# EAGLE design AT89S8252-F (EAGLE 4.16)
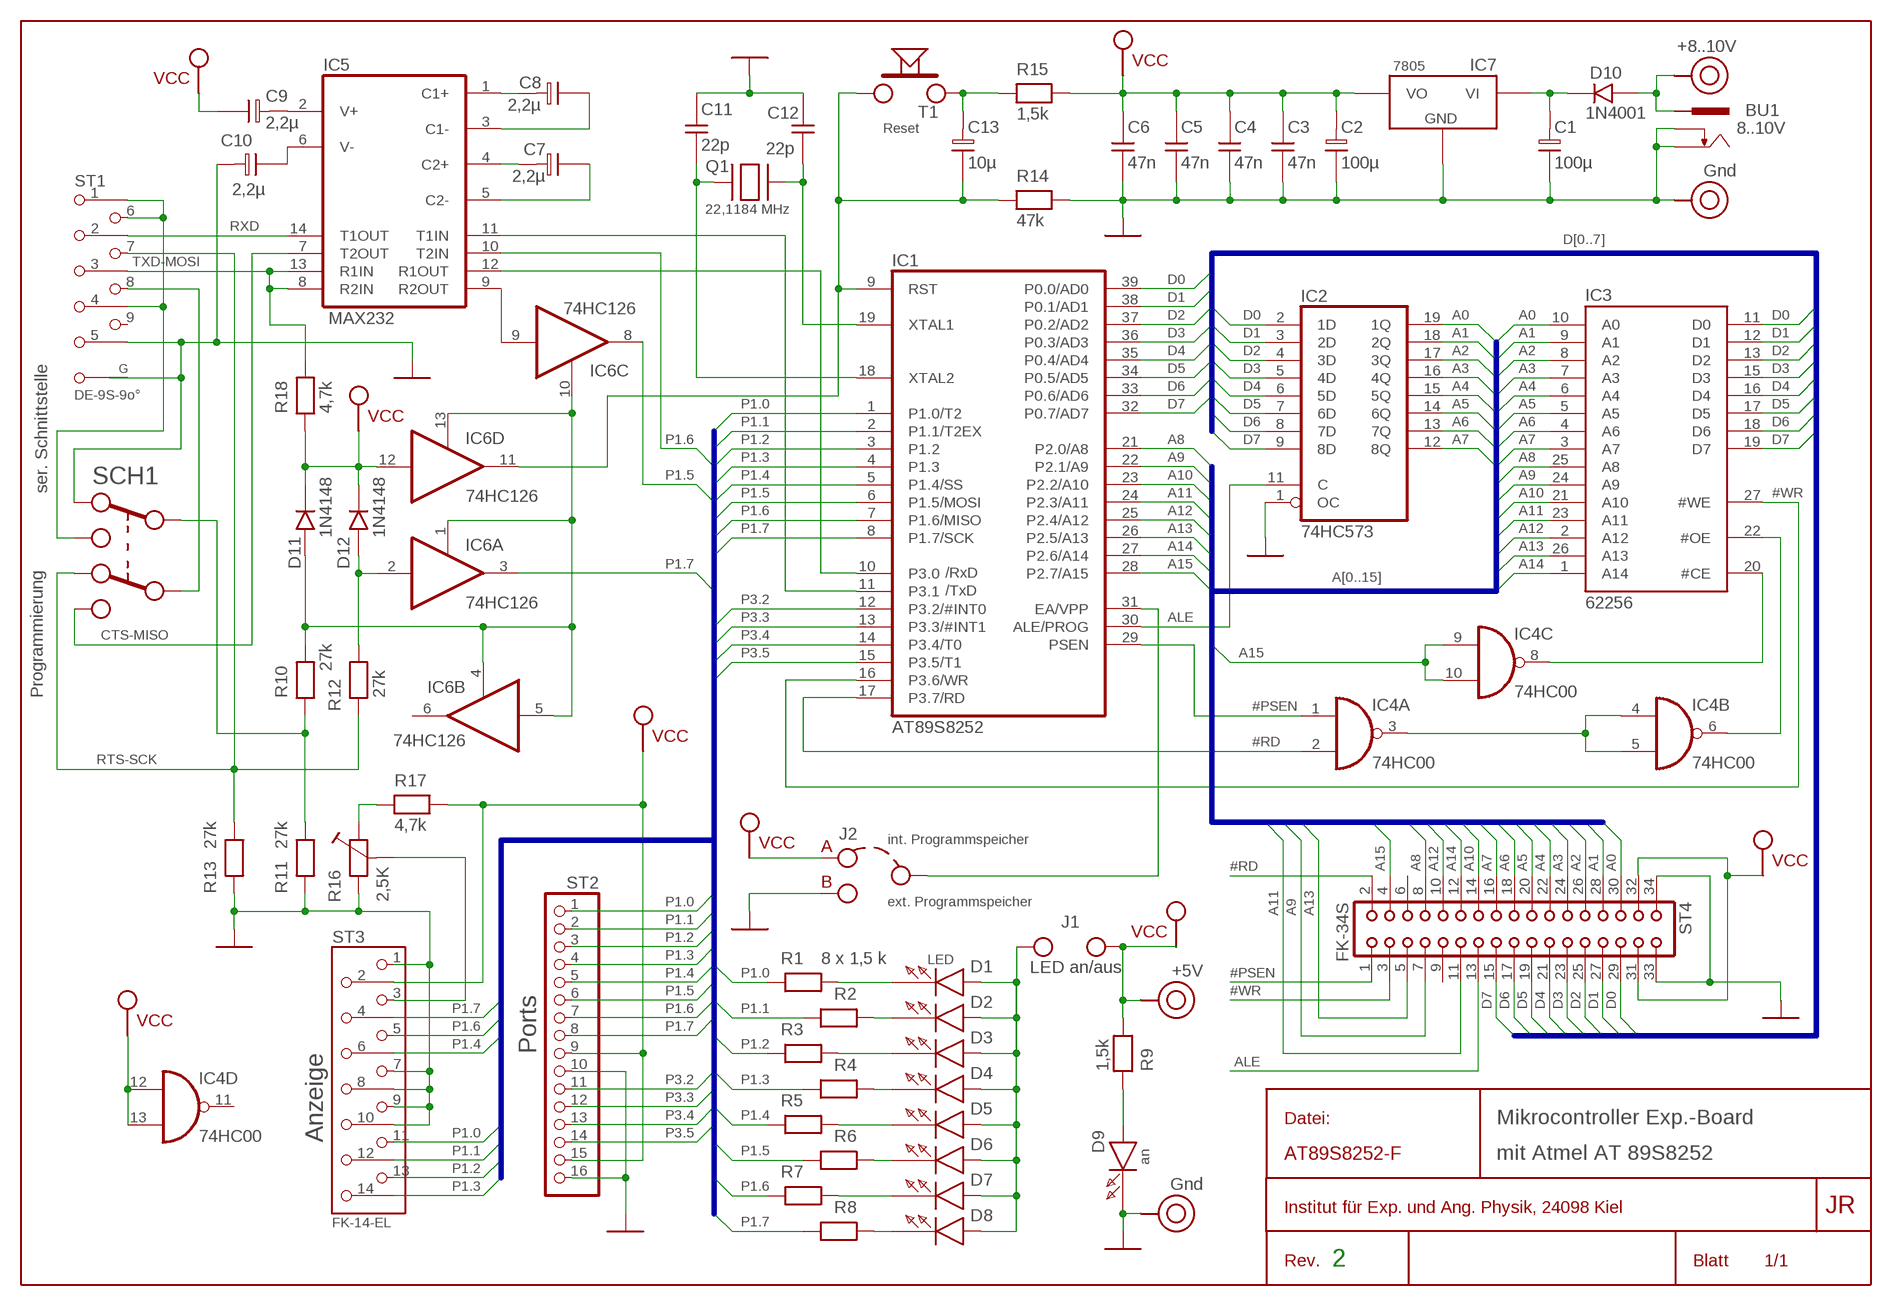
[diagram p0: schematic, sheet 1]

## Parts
BU1  8..10V  CONRAD-737992  [CONRAD-737992]
C1  100µ  ELKOR1SL  [E2,5]
C2  100µ  ELKOR1SL  [E2,5]
C3  47n  CAPR1SL  [C2,5]
C4  47n  CAPR1SL  [C2,5]
C5  47n  CAPR1SL  [C2,5]
C6  47n  CAPR1SL  [C2,5]
C7  2,2µ  ELKOR1SL  [E2,5]
C8  2,2µ  ELKOR1SL  [E2,5]
C9  2,2µ  ELKOR1SL  [E2,5]
C10  2,2µ  ELKOR1SL  [E2,5]
C11  22p  CAPR1SL  [C2,5]
C12  22p  CAPR1SL  [C2,5]
C13  10µ  ELKOR1SL  [E2,5]
D1  LEDM3-SL  [LED3]
D2  LEDM3-SL  [LED3]
D3  LEDM3-SL  [LED3]
D4  LEDM3-SL  [LED3]
D5  LEDM3-SL  [LED3]
D6  LEDM3-SL  [LED3]
D7  LEDM3-SL  [LED3]
D8  LEDM3-SL  [LED3]
D9  LEDM3-SL  [LED3]
D10  1N4001  DIODER4-SL  [D10]
D11  1N4148  DIODER3-SL  [D7,5]
D12  1N4148  DIODER3-SL  [D7,5]
IC1  AT89S8252  AT89S8252L  [LDIL-40]
IC2  74HC573  74HC573L  [LDIL-20]
IC3  62256  RAM-256KL  [LDIL-28-6]
IC4  74HC00  74HC00L  [LDIL-14]
IC5  MAX232  MAX232L  [LDIL-16]
IC6  74HC126  74HC126L  [LDIL-14]
IC7  7805  78XXTO220-SLH  [TO220H]
J1  JUMPERSL  [E1X2]
J2  DJUMPERSL  [E1X3]
Q1  22,1184 MHz  QUARZSL-V  [QV]
R1  RESR4SL  [R10]
R2  RESR4SL  [R10]
R3  RESR4SL  [R10]
R4  RESR4SL  [R10]
R5  RESR4SL  [R10]
R6  RESR4SL  [R10]
R7  RESR4SL  [R10]
R8  RESR4SL  [R10]
R9  1,5k  RESR4SL  [R10]
R10  27k  RESR4SL  [R10]
R11  27k  RESR4SL  [R10]
R12  27k  RESR4SL  [R10]
R13  27k  RESR4SL  [R10]
R14  47k  RESR4SL  [R10]
R15  1,5k  RESR4SL  [R10]
R16  2,5K  RTRIMKV-DL  [XRTRIM-V]
R17  4,7k  RESR4SL  [R10]
R18  4,7k  RESR4SL  [R10]
SCH1  SW-UM-2B  [MINSW-2B]
ST1  DE-9S-9o°  DE-9SGGHL  [D-09F90GL]
ST2  PINHD-1X16L  [1X16L]
ST3  FK-14-EL  [ML14L]
ST4  FK-34S  [ML34S]
T1  Reset  MINITASTSL  [MINITAST]
TP1  +8..10V  TPDL  [XTPV]
TP2  Gnd  TPDL  [XTPV]
TP3  +5V  TPDL  [XTPV]
TP4  Gnd  TPDL  [XTPV]

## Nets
#PSEN: IC1.29(PSEN) IC4.1(A:I0) ST4.1
#RD: IC1.17(P3.7/RD) IC4.2(A:I1) ST4.2
#WR: IC1.16(P3.6/WR) IC3.27(#WE) ST4.3
A0: IC2.19(1Q) IC3.10(A0) ST4.30
A1: IC2.18(2Q) IC3.9(A1) ST4.28
A2: IC2.17(3Q) IC3.8(A2) ST4.26
A3: IC2.16(4Q) IC3.7(A3) ST4.24
A4: IC2.15(5Q) IC3.6(A4) ST4.22
A5: IC2.14(6Q) IC3.5(A5) ST4.20
A6: IC2.13(7Q) IC3.4(A6) ST4.18
A7: IC2.12(8Q) IC3.3(A7) ST4.16
A8: IC1.21(P2.0/A8) IC3.25(A8) ST4.8
A9: IC1.22(P2.1/A9) IC3.24(A9) ST4.7
A10: IC1.23(P2.2/A10) IC3.21(A10) ST4.14
A11: IC1.24(P2.3/A11) IC3.23(A11) ST4.11
A12: IC1.25(P2.4/A12) IC3.2(A12) ST4.10
A13: IC1.26(P2.5/A13) IC3.26(A13) ST4.5
A14: IC1.27(P2.6/A14) IC3.1(A14) ST4.12
A15: IC1.28(P2.7/A15) IC4.9(C:I0) IC4.10(C:I1) ST4.4
ALE: IC1.30(ALE/PROG) IC2.11(C) ST4.13
CTS-MISO: IC5.7(T2OUT) SCH1.2B
D0: IC1.39(P0.0/AD0) IC2.2(1D) IC3.11(D0) ST4.29
D1: IC1.38(P0.1/AD1) IC2.3(2D) IC3.12(D1) ST4.27
D2: IC1.37(P0.2/AD2) IC2.4(3D) IC3.13(D2) ST4.25
D3: IC1.36(P0.3/AD3) IC2.5(4D) IC3.15(D3) ST4.23
D4: IC1.35(P0.4/AD4) IC2.6(5D) IC3.16(D4) ST4.21
D5: IC1.34(P0.5/AD5) IC2.7(6D) IC3.17(D5) ST4.19
D6: IC1.33(P0.6/AD6) IC2.8(7D) IC3.18(D6) ST4.17
D7: IC1.32(P0.7/AD7) IC2.9(8D) IC3.19(D7) ST4.15
GND: BU1.+ BU1.K C1.N C2.N C3.1 C4.1 C5.1 C6.1 C10.P C11.2 C12.2 D9.K IC2.1(OC) IC7.2(GND) J2.3 R11.1 R13.1 R14.2 R16.1 SCH1.1A ST1.5 ST1.G1 ST1.G2 ST2.10 ST2.16 ST3.1 ST3.7 ST3.8 ST3.9 ST3.10 ST4.33 ST4.34 TP2.1 TP4.1
N$1: IC1.31(EA/VPP) J2.2
N$2: SCH1.MB ST1.8
N$3: IC4.3(A:O) IC4.4(B:I0) IC4.5(B:I1)
N$4: IC3.20(#CE) IC4.8(C:O)
N$5: IC3.22(#OE) IC4.6(B:O)
N$7: C10.N IC5.6(V-)
N$8: BU1.-1 D10.A TP1.1
N$9: C1.P D10.K IC7.3(VI)
N$10: D9.A R9.1
N$11: SCH1.2A ST1.1 ST1.4 ST1.6
N$15: C8.P IC5.1(C1+)
N$16: C9.P IC5.2(V+)
N$17: C7.P IC5.4(C2+)
N$18: C8.N IC5.3(C1-)
N$19: C7.N IC5.5(C2-)
N$20: D1.K R1.1
N$21: D3.K R3.1
N$22: D5.K R5.1
N$23: D7.K R7.1
N$24: D8.K R8.1
N$25: D6.K R6.1
N$26: D4.K R4.1
N$27: D2.K R2.1
N$30: R16.2 R17.1
N$31: R10.1 R11.2 SCH1.MA
N$32: D12.A IC6.2(A:I) R12.2
N$34: IC1.11(P3.1) IC5.11(T1IN)
N$35: IC1.10(P3.0) IC5.12(R1OUT)
N$36: IC5.9(R2OUT) IC6.9(C:I)
N$37: C13.P R15.1 T1.1
N$38: C12.1 IC1.19(XTAL1) Q1.2
N$40: C11.1 IC1.18(XTAL2) Q1.1
N$42: D11.A IC6.1(A:OE) IC6.4(B:OE) IC6.5(B:I) IC6.10(C:OE) IC6.13(D:OE) R10.2
N$43: C13.N IC1.9(RST) IC6.11(D:O) R14.1 T1.2
N$44: R16.S ST3.3
N$45: D1.A D2.A D3.A D4.A D5.A D6.A D7.A D8.A J1.1
P1.0: IC1.1(P1.0/T2) R1.2 ST2.1 ST3.11
P1.1: IC1.2(P1.1/T2EX) R2.2 ST2.2 ST3.12
P1.2: IC1.3(P1.2) R3.2 ST2.3 ST3.13
P1.3: IC1.4(P1.3) R4.2 ST2.4 ST3.14
P1.4: IC1.5(P1.4/SS) R5.2 ST2.5 ST3.6
P1.5: IC1.6(P1.5/MOSI) IC6.8(C:O) R6.2 ST2.6
P1.6: IC1.7(P1.6/MISO) IC5.10(T2IN) R7.2 ST2.7 ST3.5
P1.7: IC1.8(P1.7/SCK) IC6.3(A:O) R8.2 ST2.8 ST3.4
P3.2: IC1.12(P3.2/#INT0) ST2.11
P3.3: IC1.13(P3.3/#INT1) ST2.12
P3.4: IC1.14(P3.4/T0) ST2.13
P3.5: IC1.15(P3.5/T1) ST2.14
RTS-SCK: R12.1 R13.2 SCH1.1B ST1.7
RXD: IC5.14(T1OUT) ST1.2
TXD-MOSI: IC5.8(R2IN) IC5.13(R1IN) R18.2 ST1.3
VCC: C2.P C3.2 C4.2 C5.2 C6.2 C9.N D11.K D12.K IC4.12(D:I0) IC4.13(D:I1) IC6.12(D:I) IC7.1(VO) J1.2 J2.1 R9.2 R15.2 R17.2 R18.1 ST2.9 ST2.15 ST3.2 ST4.31 ST4.32 TP3.1
Unconnected: BU1.-2 IC4.11(D:O) IC6.6(B:O) ST1.9 ST4.6 ST4.9

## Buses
D[0..7]
A[0..15]
P1.[0..7],P3.[2..5]

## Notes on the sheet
- Reset
- ser. Schnittstelle
- Programmierung
- int. Programmspeicher
- ext. Programmspeicher
- 8 x 1,5 k | LED
- LED an/aus
- Ports
- Mikrocontroller Exp.-Board
- Anzeige
- mit Atmel AT 89S8252
- an
- 2

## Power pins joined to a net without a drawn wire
GND: IC1.20(GND) IC2.10(GND) IC3.14(GND) IC4.7(P:GND) IC5.15(GND) IC6.7(P:GND)
VCC: IC1.40(VCC) IC2.20(VCC) IC3.28(VCC) IC4.14(P:VCC) IC5.16(VCC) IC6.14(P:VCC)

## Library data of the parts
BU1 = mc-parts:CONRAD-737992: FEMALE PRINT CONNECTOR DIN 45323 (34V/3A), ROKA, distributor Conrad
C1 C2 C7-C10 C13 = mc-parts:ELKO: Electrolytic capacitor
C3-C6 C11 C12 = mc-parts:CAP: Capacitor
D1-D9 = mc-parts:LED: LED
D10-D12 = mc-parts:DIODE: Diode
IC1 = MC:AT89S8252: Mikrocontroller (Atmel) mit 8kB Flash und ISP
IC2 = MC:74*573: 8-bit D latch BUS DRIVER
IC3 = MC:RAM-256K: 32x8 kBit stat. RAM
IC4 = MC:74*00: Quad 2-input NAND gate
IC5 = MC:MAX232: RS232 TRANSEIVER
IC6 = MC:74*126: Quad bus BUFFER, 3-state
IC7 = mc-parts:78XX: Postive voltage regular fix voltages
J1 = mc-parts:JUMPER: Jumper
J2 = mc-parts:DJUMPER: Alternative jumper
Q1 = mc-parts:QUARZ: Quartz
R1-R15 R17 R18 = mc-parts:RES: Resistor
R16 = mc-parts:RTRIM: Adjustable resistor
SCH1 = mc-parts:SW-UM-2
ST1 = mc-parts:DE-9SG
ST2 = mc-parts:PINHD-1X16: PIN HEADER
ST3 = mc-parts:FK-14-E: Connector with pins (male) 2 x 7 pins
ST4 = mc-parts:FK-34
T1 = mc-parts:MINITAST: Miniature push switch
TP1-TP4 = mc-parts:TP: Test or connection pin

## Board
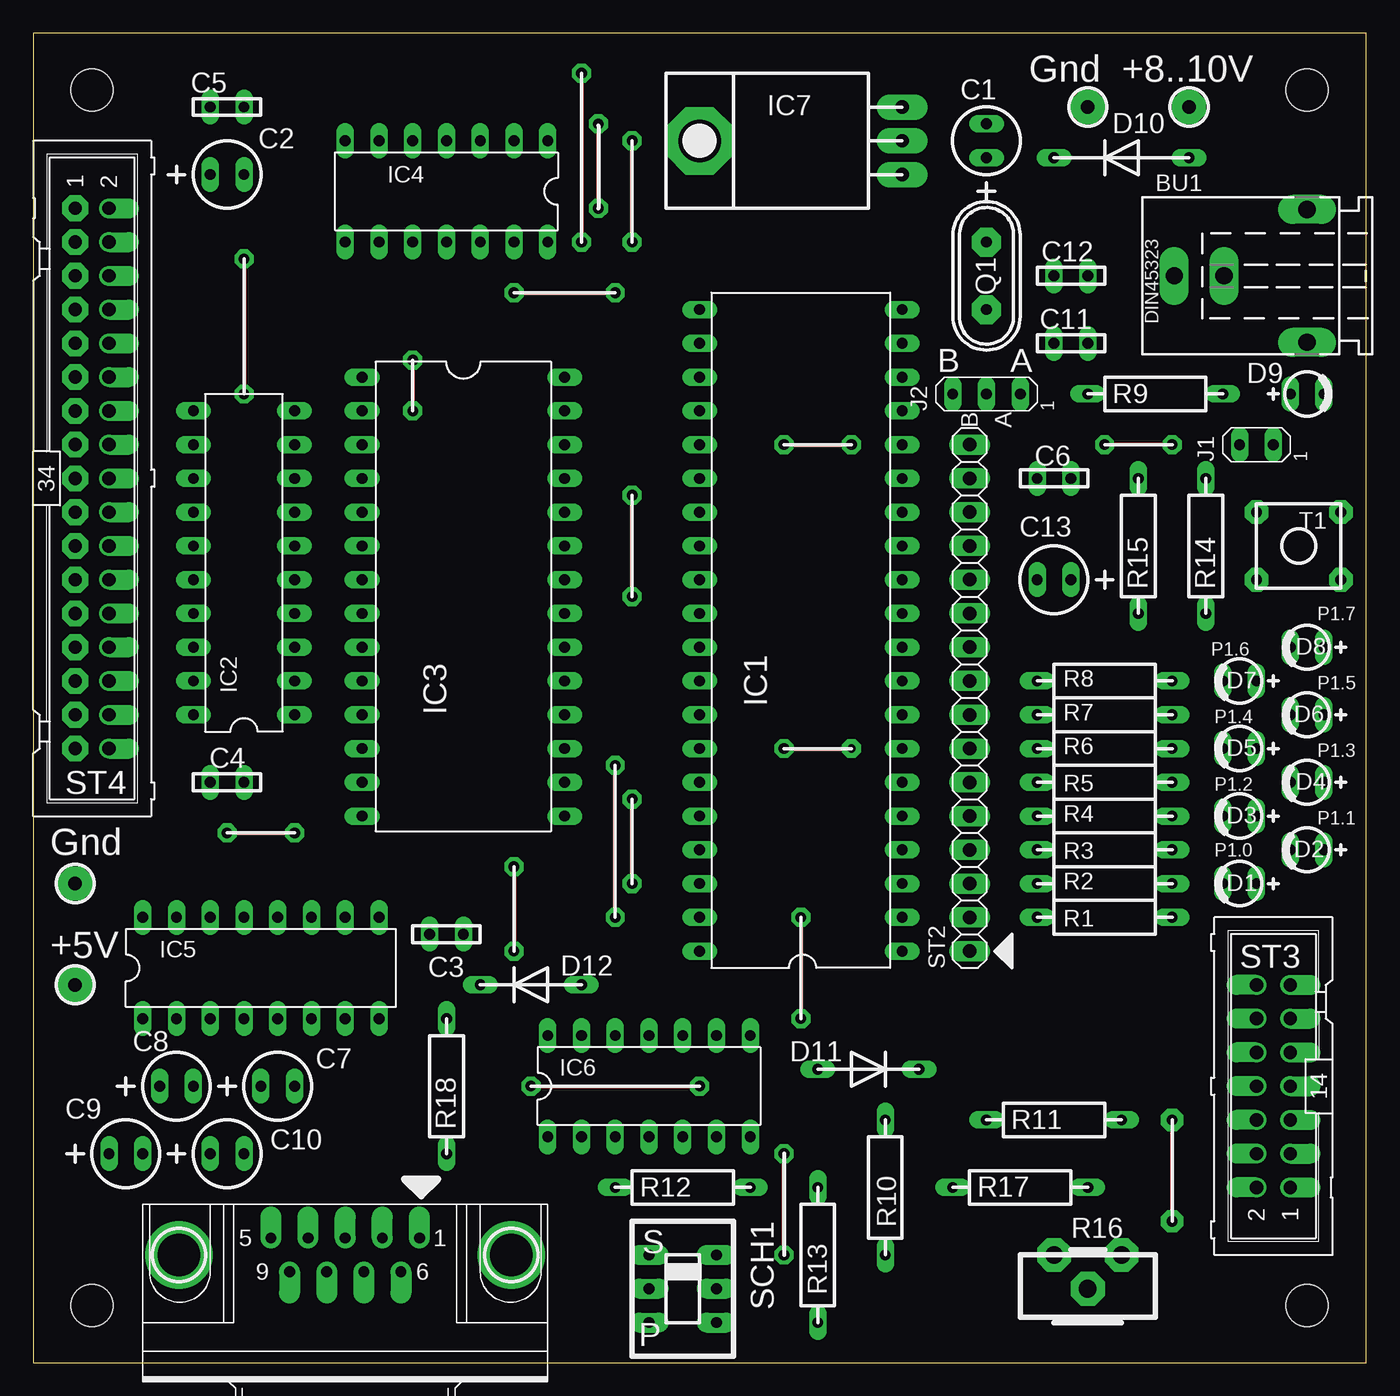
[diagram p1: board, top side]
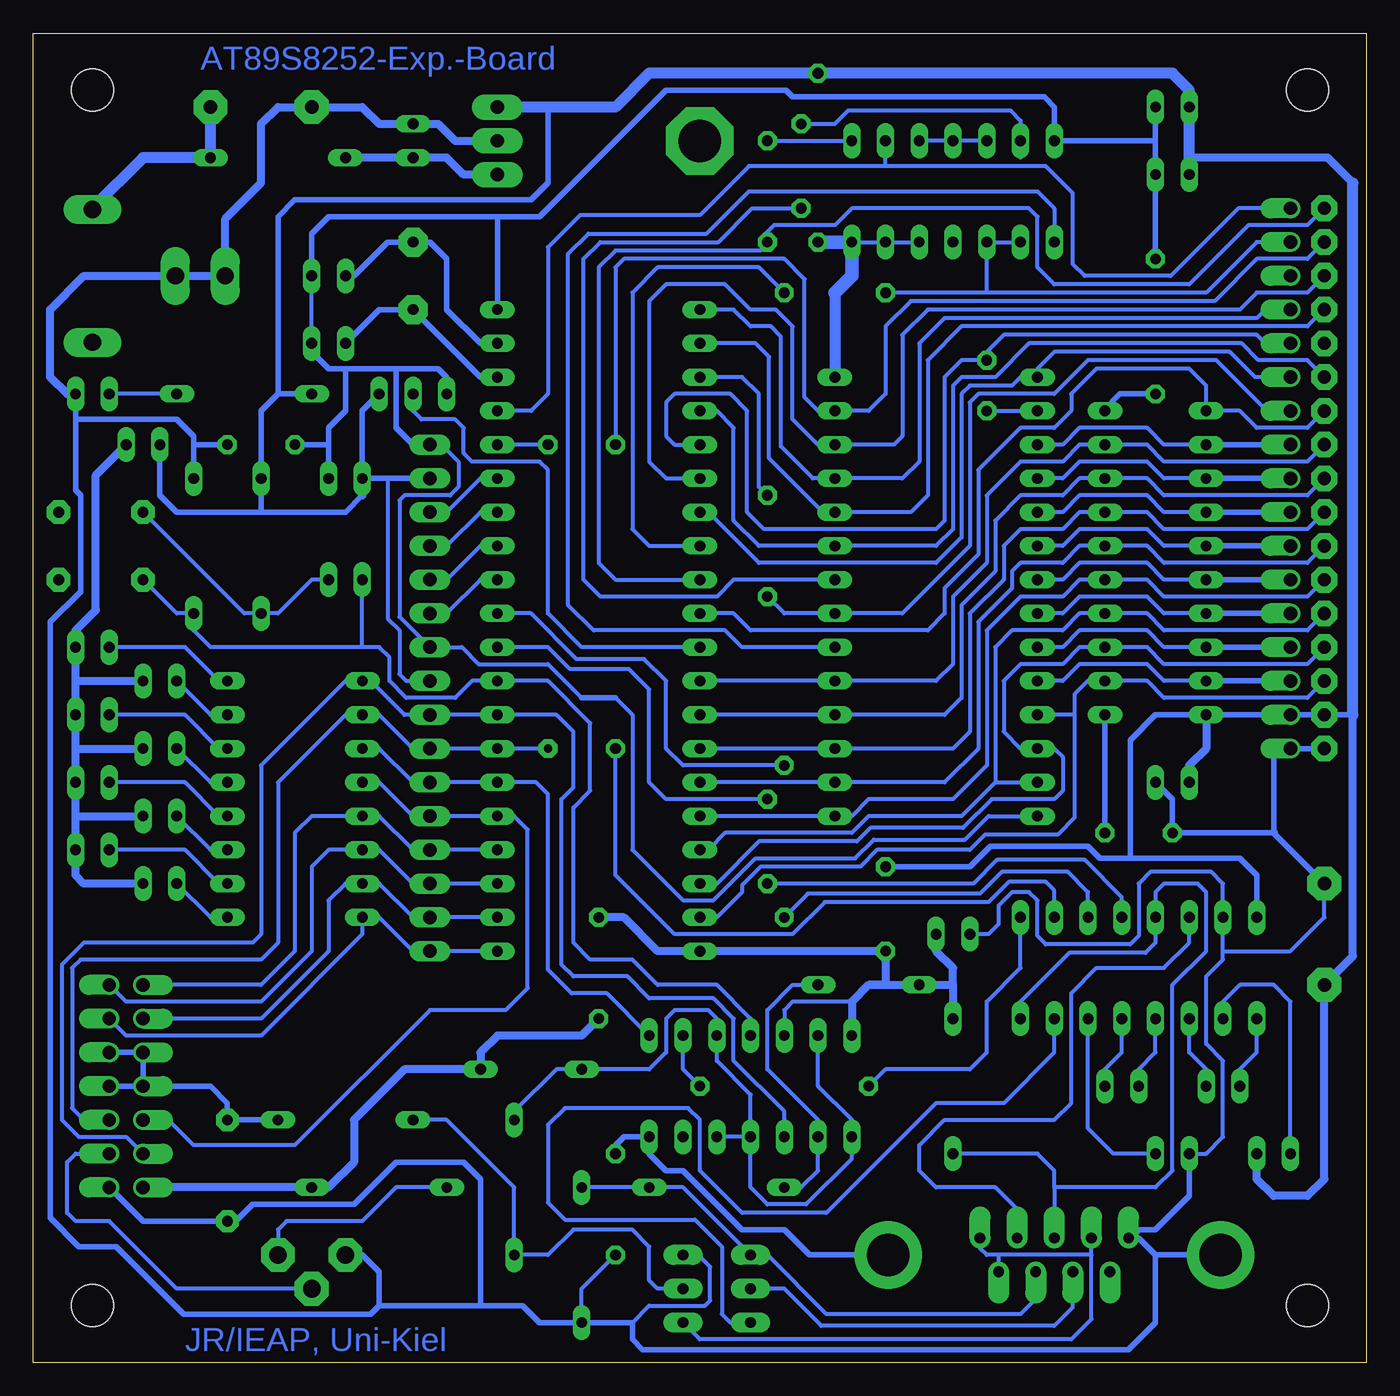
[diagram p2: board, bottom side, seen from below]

Size 100.32 x 100 mm. Coordinates in mm from the lower left corner, seen from the top.
Outline: 0,0 100.32,0 100.32,100 0,100 0,0
Copper layers (1*16): Top 0.035mm / dielectric 1.5mm / Bottom 0.035mm
Design rules "default": minimum track width 1mil, minimum drill 24mil, track to track 13mil, track to pad 13mil, pad to pad 12mil, via to via 12mil, smd to smd 8mil, copper to edge 20mil, drill to drill 8mil, minimum pad ring 10mil, minimum via ring 8mil, stop-mask expansion 4mil, vias tented up to drill 0mil, thermal gap 10mil
Holes 3.17 mm at 4.43,4.28 4.43,95.72 95.87,95.72 95.87,4.28

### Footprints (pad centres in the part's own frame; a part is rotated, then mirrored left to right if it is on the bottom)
CONRAD-737992 = drill 1.3 pad 2.184 long: + 0,10; -1 5,0; -2 -5,0; K 0,6.25
E2,5 = drill 0.813 pad 1.27 long: N 1.27,0; P -1.27,0
C2,5 = drill 0.813 pad 1.27 long: 1 1.27,0; 2 -1.27,0
LED3 = drill 0.813 long: A 1.27,0; K -1.27,0
D10 = drill 0.813 long: A 5.08,0; K -5.08,0
D7,5 = drill 0.813 long: A 3.81,0; K -3.81,0
LDIL-40 = drill 0.813 long: 1 -24.13,-7.62; 2 -21.59,-7.62; 3 -19.05,-7.62; 4 -16.51,-7.62; 5 -13.97,-7.62; 6 -11.43,-7.62; 7 -8.89,-7.62; 8 -6.35,-7.62; 9 -3.81,-7.62; 10 -1.27,-7.62; 11 1.27,-7.62; 12 3.81,-7.62; 13 6.35,-7.62; 14 8.89,-7.62; 15 11.43,-7.62; 16 13.97,-7.62; 17 16.51,-7.62; 18 19.05,-7.62; 19 21.59,-7.62; 20 24.13,-7.62; 21 24.13,7.62; 22 21.59,7.62; 23 19.05,7.62; 24 16.51,7.62; 25 13.97,7.62; 26 11.43,7.62; 27 8.89,7.62; 28 6.35,7.62; 29 3.81,7.62; 30 1.27,7.62; 31 -1.27,7.62; 32 -3.81,7.62; 33 -6.35,7.62; 34 -8.89,7.62; 35 -11.43,7.62; 36 -13.97,7.62; 37 -16.51,7.62; 38 -19.05,7.62; 39 -21.59,7.62; 40 -24.13,7.62
LDIL-20 = drill 0.813 long: 1 -11.43,-3.81; 2 -8.89,-3.81; 3 -6.35,-3.81; 4 -3.81,-3.81; 5 -1.27,-3.81; 6 1.27,-3.81; 7 3.81,-3.81; 8 6.35,-3.81; 9 8.89,-3.81; 10 11.43,-3.81; 11 11.43,3.81; 12 8.89,3.81; 13 6.35,3.81; 14 3.81,3.81; 15 1.27,3.81; 16 -1.27,3.81; 17 -3.81,3.81; 18 -6.35,3.81; 19 -8.89,3.81; 20 -11.43,3.81
LDIL-28-6 = drill 0.813 long: 1 -16.51,-7.62; 2 -13.97,-7.62; 3 -11.43,-7.62; 4 -8.89,-7.62; 5 -6.35,-7.62; 6 -3.81,-7.62; 7 -1.27,-7.62; 8 1.27,-7.62; 9 3.81,-7.62; 10 6.35,-7.62; 11 8.89,-7.62; 12 11.43,-7.62; 13 13.97,-7.62; 14 16.51,-7.62; 15 16.51,7.62; 16 13.97,7.62; 17 11.43,7.62; 18 8.89,7.62; 19 6.35,7.62; 20 3.81,7.62; 21 1.27,7.62; 22 -1.27,7.62; 23 -3.81,7.62; 24 -6.35,7.62; 25 -8.89,7.62; 26 -11.43,7.62; 27 -13.97,7.62; 28 -16.51,7.62
LDIL-14 = drill 0.813 long: 1 -7.62,-3.81; 2 -5.08,-3.81; 3 -2.54,-3.81; 4 0,-3.81; 5 2.54,-3.81; 6 5.08,-3.81; 7 7.62,-3.81; 8 7.62,3.81; 9 5.08,3.81; 10 2.54,3.81; 11 0,3.81; 12 -2.54,3.81; 13 -5.08,3.81; 14 -7.62,3.81
LDIL-16 = drill 0.813 long: 1 -8.89,-3.81; 2 -6.35,-3.81; 3 -3.81,-3.81; 4 -1.27,-3.81; 5 1.27,-3.81; 6 3.81,-3.81; 7 6.35,-3.81; 8 8.89,-3.81; 9 8.89,3.81; 10 6.35,3.81; 11 3.81,3.81; 12 1.27,3.81; 13 -1.27,3.81; 14 -3.81,3.81; 15 -6.35,3.81; 16 -8.89,3.81
TO220H = drill 1 pad 1.905 long: 1 2.54,-10.16; 2 0,-10.16; 3 -2.54,-10.16 | drill 3.2 pad 5.08 octagon: KK 0,5.08
E1X2 = drill 0.813 long: 1 0,-1.27; 2 0,1.27
E1X3 = drill 0.813 long: 1 0,-2.54; 2 0,0; 3 0,2.54
QV = drill 0.813 pad 2.184 octagon: 1 -2.54,0; 2 2.54,0
R10 = drill 0.813 long: 1 -5.08,0; 2 5.08,0
XRTRIM-V = drill 1.321 pad 2.54 octagon: 1 -2.54,-2.54; 2 -2.54,2.54; S 0,0
MINSW-2B = drill 0.813 pad 1.499 long: 1A -2.54,2.54; 1B -2.54,-2.54; 2A 2.54,2.54; 2B 2.54,-2.54; MA 0,2.54; MB 0,-2.54
D-09F90GL = drill 0.813 pad 1.575 offset: 1 -5.588,-1.27; 2 -2.794,-1.27; 3 0,-1.27; 4 2.794,-1.27; 5 5.588,-1.27; 6 -4.191,1.27; 7 -1.397,1.27; 8 1.397,1.27; 9 4.191,1.27 | drill 3.2 pad 5.08 round: G1 -12.5,0; G2 12.5,0
1X16L = drill 1.016 long: 1 -19.05,0; 2 -16.51,0; 3 -13.97,0; 4 -11.43,0; 5 -8.89,0; 6 -6.35,0; 7 -3.81,0; 8 -1.27,0; 9 1.27,0; 10 3.81,0; 11 6.35,0; 12 8.89,0; 13 11.43,0; 14 13.97,0; 15 16.51,0; 16 19.05,0
ML14L = drill 1 pad 1.422 offset: 1 -7.62,-1.27; 2 -7.62,1.27; 3 -5.08,-1.27; 4 -5.08,1.27; 5 -2.54,-1.27; 6 -2.54,1.27; 7 0,-1.27; 8 0,1.27; 9 2.54,-1.27; 10 2.54,1.27; 11 5.08,-1.27; 12 5.08,1.27; 13 7.62,-1.27; 14 7.62,1.27
ML34S = drill 1 pad 1.93 octagon: 1 -20.32,-1.27; 3 -17.78,-1.27; 5 -15.24,-1.27; 7 -12.7,-1.27; 9 -10.16,-1.27; 11 -7.62,-1.27; 13 -5.08,-1.27; 15 -2.54,-1.27; 17 0,-1.27; 19 2.54,-1.27; 21 5.08,-1.27; 23 7.62,-1.27; 25 10.16,-1.27; 27 12.7,-1.27; 29 15.24,-1.27; 31 17.78,-1.27; 33 20.32,-1.27 | drill 1 pad 1.422 offset: 2 -20.32,1.27; 4 -17.78,1.27; 6 -15.24,1.27; 8 -12.7,1.27; 10 -10.16,1.27; 12 -7.62,1.27; 14 -5.08,1.27; 16 -2.54,1.27; 18 0,1.27; 20 2.54,1.27; 22 5.08,1.27; 24 7.62,1.27; 26 10.16,1.27; 28 12.7,1.27; 30 15.24,1.27; 32 17.78,1.27; 34 20.32,1.27
MINITAST = drill 0.813 pad 1.778 octagon: 1 -2.54,-3.175; 2 2.54,-3.175; 3 2.54,3.175; 4 -2.54,3.175
XTPV = drill 1.016 pad 2.54 octagon: 1 0,0

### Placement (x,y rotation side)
BU1  95.87,81.75 90 top
C1  71.74,91.91 90 top
C2  14.59,89.37 0 top
C3  31.1,32.22 180 top
C4  14.59,43.65 0 top
C5  14.59,94.45 0 top
C6  76.82,66.51 0 top
C7  18.4,20.79 0 top
C8  10.78,20.79 0 top
C9  6.97,15.71 0 top
C10  14.59,15.71 0 top
C11  78.09,76.67 180 top
C12  78.09,81.75 180 top
C13  76.82,58.89 180 top
D1  90.79,36.03 0 top
D2  95.87,38.57 0 top
D3  90.79,41.11 0 top
D4  95.87,43.65 0 top
D5  90.79,46.19 0 top
D6  95.87,48.73 0 top
D7  90.79,51.27 0 top
D8  95.87,53.81 0 top
D9  95.87,72.86 180 top
D10  81.9,90.64 0 top
D11  62.85,22.06 180 top
D12  37.45,28.41 0 top
IC1  57.77,55.08 90 top
IC2  15.86,60.16 90 top
IC3  32.37,57.62 270 top
IC4  31.1,88.1 180 top
IC5  17.13,29.68 0 top
IC6  46.34,20.79 0 top
IC7  55.23,91.91 90 top
J1  92.06,69.05 90 top
J2  71.74,72.86 90 top
Q1  71.74,81.75 90 top
R1  80.63,33.49 180 top
R2  80.63,36.03 180 top
R3  80.63,38.57 180 top
R4  80.63,41.11 180 top
R5  80.63,43.65 180 top
R6  80.63,46.19 180 top
R7  80.63,48.73 180 top
R8  80.63,51.27 180 top
R9  84.44,72.86 180 top
R10  64.12,13.17 90 top
R11  76.82,18.25 180 top
R12  48.88,13.17 180 top
R13  59.04,8.09 90 top
R14  88.25,61.43 90 top
R15  83.17,61.43 90 top
R16  79.36,5.55 270 top
R17  74.28,13.17 0 top
R18  31.1,20.79 270 top
SCH1  48.88,5.55 270 top
ST1  23.48,8.09 180 top
ST2  70.47,50 90 top
ST3  93.33,20.79 90 top
ST4  4.43,66.51 270 top
T1  95.23,61.43 270 top
TP1  86.98,94.45 0 top
TP2  79.36,94.45 0 top
TP3  3.16,28.41 0 top
TP4  3.16,36.03 0 top
U$21  [IEAP-TOP]  not placed on the board

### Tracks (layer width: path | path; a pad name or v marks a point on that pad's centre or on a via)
#PSEN  (via drill 0.8 pad 1.42)
  Top 0.305: v45.07,84.29 v45.07,91.91
  Bottom 0.305: IC1.29 56.5,58.89 57.77,60.16 57.77,82.39 56.5,83.66 45.58,83.66 45.07,84.16 v45.07,84.29 45.2,84.42 45.2,84.92 44.56,85.56 39.99,85.56 38.72,86.83 25.39,86.83 24.75,86.19 24.75,82.39 23.48,81.11 13.32,81.11 8.88,85.56 4.43,85.56 ST4.1 | v45.07,91.91 IC4.1
#RD
  Bottom 0.305: IC1.17 62.85,71.59 61.58,72.86 61.58,83.91 59.17,86.32 50.15,86.32 46.47,90 36.18,90 | ST4.2 9.64,86.83 14.72,81.75 21.19,81.75 22.08,82.64 22.08,87.97 24.12,90 36.18,90 | 36.18,90 IC4.2
#WR  (via drill 0.8 pad 1.42)
  Top 0.305: v56.5,69.05 v61.58,69.05
  Bottom 0.305: v61.58,69.05 IC1.16 | v56.5,69.05 56.5,82.39 55.86,83.02 43.8,83.02 42.28,81.5 42.28,72.61 41.26,71.59 IC3.27 37.45,71.59 36.18,72.86 36.18,77.94 34.27,79.84 11.41,79.84 8.24,83.02 4.43,83.02 ST4.3
A0
  Bottom 0.305: IC2.19 15.22,51.27 16.5,52.54 21.57,52.54 22.85,51.27 IC3.10
  Bottom 0.406: ST4.30 IC2.19
A1
  Bottom 0.305: IC2.18 15.22,53.81 16.5,55.08 21.57,55.08 22.85,53.81 IC3.9
  Bottom 0.406: ST4.28 IC2.18
A2
  Bottom 0.305: IC2.17 15.22,56.35 16.5,57.62 21.57,57.62 22.85,56.35 IC3.8
  Bottom 0.406: ST4.26 IC2.17
A3
  Bottom 0.305: IC2.16 15.22,58.89 16.5,60.16 21.57,60.16 22.85,58.89 IC3.7
  Bottom 0.406: ST4.24 IC2.16
A4
  Bottom 0.305: IC2.15 15.22,61.43 16.5,62.7 21.57,62.7 22.85,61.43 IC3.6
  Bottom 0.406: ST4.22 IC2.15
A5
  Bottom 0.305: IC2.14 15.22,63.97 16.5,65.24 21.57,65.24 22.85,63.97 IC3.5
  Bottom 0.406: ST4.20 IC2.14
A6
  Bottom 0.305: IC2.13 15.22,66.51 16.5,67.78 21.57,67.78 22.85,66.51 IC3.4
  Bottom 0.406: ST4.18 IC2.13
A7
  Bottom 0.305: IC2.12 15.22,69.05 16.5,70.32 21.57,70.32 22.85,69.05 IC3.3
  Bottom 0.406: ST4.16 IC2.12
A8
  Bottom 0.305: IC1.21 47.61,79.21 46.34,77.94 44.82,77.94 44.05,77.18 44.05,68.92 41.64,66.51 IC3.25 34.91,66.51 33.64,67.78 33.64,76.67 31.73,78.58 8.24,78.58 7.61,79.21 ST4.8
A9
  Bottom 0.305: IC1.22 45.96,76.67 44.94,75.65 44.94,68.03 40.88,63.97 IC3.24 34.27,63.97 33,65.24 33,75.4 30.46,77.94 4.43,77.94 ST4.7
A10  (via drill 0.8 pad 1.42)
  Top 0.305: v45.07,57.62 v45.07,65.24
  Bottom 0.305: v45.07,57.62 43.8,56.35 IC3.21 34.91,56.35 29.83,61.43 29.83,72.22 29.2,72.86 23.48,72.86 20.94,75.4 11.29,75.4 7.48,71.59 ST4.14 | v45.07,65.24 45.7,65.88 45.7,72.86 46.97,74.13 IC1.23
A11
  Bottom 0.305: IC1.24 48.88,71.59 47.61,70.32 47.61,63.34 45.7,61.43 IC3.23 32.37,61.43 31.1,62.7 31.1,73.5 30.46,74.13 27.93,74.13 25.39,76.67 9.38,76.67 8.11,75.4 4.43,75.4 ST4.11
A12  (via drill 0.8 pad 1.42)
  Top 0.305: v28.56,75.4 v28.56,71.59
  Bottom 0.305: 24.12,71.59 IC3.2 v28.56,71.59 | IC1.25 52.05,69.05 52.69,69.69 52.69,72.22 52.05,72.86 47.86,72.86 46.59,71.59 46.59,63.97 45.32,62.7 32.37,62.7 31.73,63.34 31.73,74.13 30.46,75.4 v28.56,75.4 28.56,76.03 27.29,77.3 8.24,77.3 7.61,76.67 ST4.10
A13
  Bottom 0.305: IC1.26 52.69,66.51 53.96,67.78 53.96,79.84 52.69,81.11 48.24,81.11 46.34,79.21 44.43,79.21 43.16,77.94 43.16,70.95 41.26,69.05 IC3.26 35.54,69.05 34.91,69.69 34.91,77.3 33,79.21 9.51,79.21 8.24,80.48 4.43,80.48 ST4.5
A14
  Bottom 0.305: IC1.27 49.52,63.97 45.7,60.16 32.37,60.16 30.46,62.06 30.46,72.86 29.83,73.5 26.66,73.5 26.02,74.13 IC3.1 24.75,74.77 23.48,76.03 10.27,76.03 8.37,74.13 ST4.12
A15  (via drill 0.8 pad 1.42)
  Top 0.305: v36.18,80.48 v43.8,80.48
  Bottom 0.305: IC1.28 53.96,61.43 55.23,62.7 55.23,80.48 53.32,82.39 45.7,82.39 v43.8,80.48 | 28.56,80.48 v36.18,80.48 | 28.56,80.48 12.05,80.48 8.24,84.29 ST4.4 | IC4.9 IC4.10 28.56,80.48
ALE
  Bottom 0.305: IC1.30 47.61,56.35 46.34,55.08 33,55.08 31.73,56.35 31.73,58.25 29.2,60.8 29.2,67.14 26.02,70.32 23.48,70.32 22.21,71.59 22.21,72.86 20.3,74.77 13.32,74.77 12.05,73.5 IC2.11 9.51,71.59 8.24,70.32 4.43,70.32 ST4.13
CTS-MISO
  Bottom 0.305: SCH1.2B 47.86,3.01 48.5,3.64 48.5,8.73 50.53,10.76 60.31,10.76 61.58,12.03 61.58,17.87 60.31,19.14 51.04,19.14 50.15,18.25 50.15,14.44 46.97,11.27 40.62,11.27 32.37,19.52 27.29,19.52 23.48,23.33 IC5.7
D0
  Bottom 0.305: IC1.39 48.88,33.49 46.97,35.39 46.97,35.9 45.58,37.3 38.09,37.3 36.81,38.57 29.83,38.57 28.69,39.71 23.23,39.71 21.96,40.98 21.96,48.73 | 21.96,48.73 IC3.11 | 21.96,48.73 21.96,50.25 20.94,51.27 IC2.2 16.5,51.27 15.22,50 4.43,50 ST4.29
D1
  Bottom 0.305: IC1.38 48.88,36.03 45.7,39.2 38.34,39.2 37.32,40.22 30.34,40.22 28.18,42.38 23.48,42.38 22.85,43.02 22.85,45.55 23.48,46.19 IC3.12 26.02,46.19 27.29,47.46 27.29,51.27 26.02,52.54 22.85,52.54 21.57,53.81 IC2.3 16.5,53.81 15.22,52.54 4.43,52.54 ST4.27
D2
  Bottom 0.305: 27.93,43.65 27.93,53.81 26.66,55.08 22.85,55.08 21.57,56.35 IC2.4 16.5,56.35 15.22,55.08 4.43,55.08 ST4.25 | 27.93,43.65 IC3.13 | IC1.37 49.52,38.57 48.24,39.84 38.72,39.84 37.45,41.11 30.46,41.11 27.93,43.65
D3
  Bottom 0.305: 20.3,58.89 21.57,58.89 22.85,57.62 26.02,57.62 28.56,55.08 28.56,44.92 31.1,42.38 37.45,42.38 38.72,41.11 IC3.15 IC1.36 | 20.3,58.89 IC2.5 | ST4.23 4.43,57.62 15.22,57.62 16.5,58.89 20.3,58.89
D4
  Bottom 0.305: IC1.35 IC3.16 31.73,43.65 29.2,46.19 29.2,55.71 26.66,58.25 26.66,59.52 26.02,60.16 22.85,60.16 21.57,61.43 IC2.6 16.5,61.43 15.22,60.16 4.43,60.16 ST4.21
D5
  Bottom 0.305: IC1.34 IC3.17 31.1,46.19 29.83,47.46 29.83,56.35 27.29,58.89 27.29,61.43 26.02,62.7 22.85,62.7 21.57,63.97 IC2.7 16.5,63.97 15.22,62.7 4.43,62.7 ST4.19
D6
  Bottom 0.305: IC1.33 IC3.18 31.73,48.73 30.46,50 30.46,56.98 27.93,59.52 27.93,63.34 26.02,65.24 22.85,65.24 21.57,66.51 IC2.8 16.5,66.51 15.22,65.24 4.43,65.24 ST4.17
D7
  Bottom 0.305: IC1.32 IC3.19 32.37,51.27 31.1,52.54 31.1,57.62 28.56,60.16 28.56,65.24 26.02,67.78 22.85,67.78 21.57,69.05 IC2.9 16.5,69.05 15.22,67.78 4.43,67.78 ST4.15
GND  (via drill 0.8 pad 1.42, 0.8 pad 1.68)
  Top 0.305: v14.59,39.84 v19.67,39.84 | v85.71,10.63 v85.71,18.25 | v15.86,83.02 v15.86,72.86 | v85.71,69.05 v80.63,69.05 | v56.5,8.09 v56.5,15.71
  Bottom 0.305: v56.5,8.09 59.04,5.55 R13.1 59.04,2.88 58.91,3.01 | 10.78,30.95 10.78,30.31 12.05,29.04 12.05,23.96 10.78,22.7 10.78,16.98 12.05,15.71 C10.P | 10.78,30.95 IC5.15 10.78,36.03 11.67,36.92 16.24,36.92 17.13,36.03 17.13,32.09 17.77,31.46 24.12,31.46 24.75,32.09 24.75,34.76 25.39,35.39 26.66,35.39 27.67,34.38 27.67,32.98 28.43,32.22 C3.1 | 10.78,30.95 5.7,30.95 3.16,33.49 TP4.1 | IC3.14 28.43,41.11 30.21,39.33 37.07,39.33 38.47,37.94 45.96,37.94 49.13,34.76 51.42,34.76 55.23,38.57 55.23,48.73 56.5,50 | 59.04,50 61.58,52.54 66.79,52.54 68.06,53.81 ST2.10 72.76,56.1 72.76,64.86 72.38,65.24 68.95,65.24 68.31,65.88 68.31,67.78 69.58,69.05 ST2.16 | SCH1.1A 50.28,8.09 49.39,7.2 49.39,4.66 49.77,4.28 53.96,4.28 55.23,3.01 | C11.2 79.49,76.8 79.36,76.92 C12.2
  Bottom 0.406: ST2.16 71.74,69.05 73.01,70.32 73.01,74.77 | 73.01,74.77 69.84,74.77 69.2,74.13 J2.3 | C11.2 79.36,76.03 78.09,74.77 76.82,74.77 | 76.82,74.77 73.01,74.77 | C12.2 79.36,84.92 78.09,86.19 65.39,86.19 | ST3.9 ST3.10 ST3.8 | ST3.8 ST3.7 | ST3.8 86.98,20.79 85.71,19.52 v85.71,18.25 R11.1 | ST3.1 92.06,10.63 v85.71,10.63 85.08,10.63 83.81,11.9 76.19,11.9 73.01,15.08 67.93,15.08 66.66,13.81 66.66,4.28 | R13.1 62.21,3.01 63.48,4.28 66.66,4.28 | v56.5,15.71 56.5,16.34 55.86,16.98 IC6.7 53.96,15.71 52.69,14.44 51.42,14.44 46.97,10 43.8,10 41.89,8.09 ST1.G1 | C10.P 13.32,12.54 15.86,10 17.13,10 17.77,9.36 ST1.5 17.13,9.36 15.86,8.09 | 15.86,8.09 ST1.G2 | C4.1 14.59,42.38 v14.59,39.84 6.97,39.84 6.91,39.78 | TP4.1 6.91,39.78 | v19.67,39.84 IC2.1 | ST4.34 5.95,46.19 | ST4.34 ST4.33 | ST4.34 6.97,46.19 6.97,39.97 6.84,39.84 6.91,39.78 | IC2.10 19.67,71.72 18.53,72.86 v15.86,72.86 | 15.73,83.02 v15.86,83.02 C2.N 15.86,91.91 | 15.86,91.91 C5.1 | 15.86,91.91 IC4.7 23.48,94.45 24.24,95.21 43.16,95.21 43.67,95.72 52.69,95.72 62.21,86.19 65.39,86.19 | 59.04,50 56.5,50 | 66.66,4.28 74.28,4.28 | 74.28,4.28 74.92,3.64 89.01,3.64 94.09,8.73 96.89,8.73 99.05,10.88 99.05,55.71 96.76,58 96.76,65.24 97.14,65.62 97.14,70.95 | 97.14,70.95 D9.K | R16.1 75.55,8.09 74.28,6.82 74.28,4.28 | 78.09,69.05 78.09,70.32 76.82,71.59 76.82,74.77 | 78.09,69.05 C6.1 | v80.63,69.05 78.09,69.05 | 15.86,8.09 15.86,3.01 17.89,0.98 54.47,0.98 55.23,1.74 55.23,3.01 58.91,3.01 | 65.39,86.19 IC1.20 | 88.25,69.05 88.25,69.69 89.52,70.95 97.14,70.95 | 88.25,69.05 R14.2 | 88.25,69.05 v85.71,69.05
  Bottom 0.61: IC7.2 68.56,91.91 69.84,93.18 C1.N 74.28,93.18 75.55,94.45 TP2.1 81.9,94.45 83.17,93.18 83.17,88.73 85.87,86.03 BU1.+ BU1.K 96.51,81.75 99.05,79.21 99.05,74.13 97.78,72.86 D9.K
N$1
  Bottom 0.305: J2.2 71.74,71.59 71.11,70.95 68.56,70.95 67.93,70.32 67.93,68.41 67.3,67.78 62.21,67.78 61.58,67.14 61.58,56.35 59.04,53.81 IC1.31
N$2
  Bottom 0.305: SCH1.MB 43.8,5.55 41.01,2.76 23.48,2.76 22.08,4.15 ST1.8
N$3
  Bottom 0.305: IC4.3 IC4.4 IC4.5
N$4
  Bottom 0.305: IC3.20 46.97,53.81 48.24,55.08 58.15,55.08 60.06,56.98 60.06,83.4 58.53,84.92 49.64,84.92 46.47,88.1 24.75,88.1 23.48,86.83 IC4.8
N$5  (via drill 0.8 pad 1.42)
  Top 0.305: v42.53,86.83 v42.53,93.18
  Bottom 0.305: IC3.22 47.61,58.89 48.88,57.62 57.64,57.62 58.91,58.89 58.91,83.02 57.64,84.29 48.75,84.29 46.21,86.83 v42.53,86.83 | 26.02,90.64 IC4.6 26.02,93.43 26.78,94.2 38.97,94.2 39.99,93.18 v42.53,93.18
N$6  (via drill 0.61 pad 1.02)
  other vias: 4.43,95.72
N$7
  Bottom 0.305: C10.N 19.04,15.71 20.94,17.61 IC5.6
N$8
  Bottom 0.813: TP1.1 D10.A 92.06,90.64 95.87,86.83 BU1.-1
N$9
  Bottom 0.61: IC7.3 67.93,89.37 69.2,90.64 C1.P D10.K
N$10
  Bottom 0.305: R9.1 D9.A
N$11
  Bottom 0.305: SCH1.2A 50.15,1.74 22.21,1.74 20.69,3.26 20.69,8.09 | 20.69,8.09 ST1.4 | ST1.1 29.07,8.6 28.56,8.09 27.67,8.09 | 27.67,8.09 ST1.6 | 20.69,8.09 27.67,8.09
N$12  (via drill 0.61 pad 1.02)
  other vias: 4.43,4.28
N$13  (via drill 0.61 pad 1.02)
  other vias: 95.87,4.28
N$14  (via drill 0.61 pad 1.02)
  other vias: 95.87,95.72
N$15
  Bottom 0.305: C8.P 9.51,22.06 8.24,23.33 IC5.1
N$16
  Bottom 0.305: C9.P 5.7,27.14 6.97,28.41 9.51,28.41 10.78,27.14 IC5.2
N$17
  Bottom 0.305: C7.P 17.13,22.06 15.86,23.33 IC5.4
N$18
  Bottom 0.305: C8.N 12.05,22.06 13.32,23.33 IC5.3
N$19
  Bottom 0.305: C7.N 19.67,22.06 18.4,23.33 IC5.5
N$20
  Bottom 0.305: R1.1 86.98,33.49 D1.K
N$21
  Bottom 0.305: R3.1 86.98,38.57 D3.K
N$22
  Bottom 0.305: R5.1 86.98,43.65 D5.K
N$23
  Bottom 0.305: R7.1 86.98,48.73 D7.K
N$24
  Bottom 0.305: R8.1 86.34,51.27 88.89,53.81 D8.K
N$25
  Bottom 0.305: R6.1 86.34,46.19 88.89,48.73 D6.K
N$26
  Bottom 0.305: R4.1 86.34,41.11 88.89,43.65 D4.K
N$27
  Bottom 0.305: R2.1 86.34,36.03 88.89,38.57 D2.K
N$30
  Bottom 0.305: R17.1 73.01,13.17 75.55,10.63 81.27,10.63 81.9,10 R16.2
N$31
  Bottom 0.305: R11.2 69.2,18.25 64.12,13.17 R10.1 61.58,8.09 59.67,10 55.23,10 53.96,8.73 53.96,6.18 53.32,5.55 SCH1.MA
N$32
  Bottom 0.305: R12.2 42.53,13.17 41.26,14.44 IC6.2 41.26,18.25 45.07,22.06 45.07,26.5 43.16,28.41 D12.A
N$34  (via drill 0.8 pad 1.42)
  Top 0.305: v43.8,33.49 v43.8,44.92
  Bottom 0.305: IC5.11 20.94,35.39 22.46,36.92 27.42,36.92 29.07,35.27 42.02,35.27 v43.8,33.49 | v43.8,44.92 51.42,44.92 52.69,46.19 52.69,51.27 54.34,52.92 59.42,52.92 62.85,56.35 IC1.11
N$35  (via drill 0.8 pad 1.42)
  Top 0.305: v45.07,36.03 v45.07,42.38
  Bottom 0.305: IC5.12 18.4,35.01 21.19,37.81 27.8,37.81 29.58,36.03 v45.07,36.03 | v45.07,42.38 52.69,42.38 53.96,43.65 53.96,50.63 55.48,52.16 59.93,52.16 61.58,53.81 IC1.10
N$36  (via drill 0.8 pad 1.42)
  Top 0.305: v37.45,20.79 v50.15,20.79
  Bottom 0.305: IC5.9 26.02,29.68 28.56,27.14 28.56,23.33 29.83,22.06 36.18,22.06 v37.45,20.79 | IC6.9 51.42,22.06 v50.15,20.79
N$37
  Bottom 0.305: C13.P 79.36,58.89 81.9,56.35 R15.1 84.44,56.35 T1.1
N$38
  Bottom 0.406: IC1.19 66.66,76.67 69.2,79.21 69.2,83.02 70.47,84.29 Q1.2 73.65,84.29 76.19,81.75 C12.1
N$40
  Bottom 0.406: IC1.18 66.66,74.13 Q1.1 74.28,79.21 C11.1
N$42
  Bottom 0.305: IC6.4 IC6.5 IC6.4 | IC6.13 41.26,20.79 38.72,18.25 IC6.1 38.72,15.33 42.15,11.9 45.07,11.9 46.34,13.17 IC6.4 | IC6.4 46.34,20.15 48.88,22.7 | 48.88,22.7 IC6.10 | 48.88,22.7 48.88,25.87 49.52,26.5 52.05,26.5 52.69,25.87 52.69,23.33 53.96,22.06 D11.A 60.95,22.06 64.12,18.88 R10.2
N$43
  Bottom 0.305: 74.28,53.81 73.52,53.05 73.52,51.27 72.25,50 68.56,50 67.3,51.27 IC1.9 61.58,51.27 58.4,48.09 58.4,43.02 59.67,41.74 59.67,31.58 58.4,30.31 55.23,30.31 53.32,28.41 48.88,28.41 46.34,25.87 IC6.11 | 74.28,53.81 75.55,53.81 C13.N | 74.28,53.81 86.98,53.81 88.25,55.08 R14.1 89.52,56.35 T1.2
N$44
  Bottom 0.305: ST3.3 97.14,15.71 97.78,15.08 97.78,11.27 97.14,10.63 94.6,10.63 89.52,5.55 R16.S
N$45
  Bottom 0.61: 97.14,51.27 D7.A | 97.14,51.27 D8.A 97.14,55.08 95.62,56.6 95.62,66.76 J1.1 | 97.14,51.27 D6.A 97.14,46.19 | 97.14,46.19 D4.A 97.14,41.11 | 97.14,41.11 D2.A 97.14,36.66 96.51,36.03 D1.A | 97.14,41.11 D3.A | 97.14,46.19 D5.A
P1.0
  Bottom 0.305: IC1.1 ST2.1 71.74,30.95 74.28,33.49 R1.2 75.55,32.22 83.17,24.6 93.33,24.6 ST3.11
P1.1
  Bottom 0.305: IC1.2 ST2.2 71.74,33.49 74.28,36.03 R2.2 76.82,36.03 78.09,34.76 78.09,30.95 83.17,25.87 ST3.12
P1.2
  Bottom 0.305: IC1.3 ST2.3 71.74,36.03 74.28,38.57 R3.2 78.09,38.57 79.36,37.3 79.36,30.95 83.17,27.14 93.33,27.14 ST3.13
P1.3
  Bottom 0.305: IC1.4 ST2.4 71.74,38.57 74.28,41.11 R4.2 79.36,41.11 80.63,39.84 80.63,30.95 83.17,28.41 ST3.14
P1.4
  Bottom 0.305: R5.2 74.28,43.65 71.74,41.11 ST2.5 IC1.5 64.12,41.11 63.1,40.09 63.1,28.16 64.76,26.5 70.47,26.5 80.63,16.34 88.25,16.34 90.16,18.25 ST3.6
P1.5
  Bottom 0.305: IC6.8 57.13,27.77 59.8,27.77 61.58,29.55 61.58,42.76 62.47,43.65 IC1.6 ST2.6 71.74,43.65 74.28,46.19 R6.2
P1.6  (via drill 0.61 pad 1.42, 0.8 pad 1.42)
  Top 0.305: v56.5,46.19 v61.58,46.19
  Bottom 0.305: IC5.10 23.48,35.52 24.12,36.16 26.91,36.16 28.43,34.63 40.75,34.63 43.16,32.22 52.05,32.22 56.5,36.66 v56.5,46.19 | v61.58,46.19 IC1.7 ST2.7 71.74,46.19 74.28,48.73 R7.2 76.82,48.73 81.9,43.65 81.9,31.58 83.17,30.31 96.76,30.31 97.39,29.68 97.39,19.14 96.51,18.25 ST3.5
P1.7
  Bottom 0.305: IC6.3 43.8,18.88 47.61,22.7 47.61,25.87 49.13,27.39 53.96,27.39 55.61,29.04 59.67,29.04 60.56,29.93 60.56,42.38 59.67,43.27 59.67,47.46 60.95,48.73 IC1.8 ST2.8 72.38,48.73 74.92,51.27 R8.2 76.82,51.27 83.17,44.92 83.17,32.22 83.81,31.58 96.51,31.58 98.16,29.93 98.16,18.25 96.89,16.98 93.33,16.98 ST3.4
P3.2
  Bottom 0.305: IC1.12 66.66,58.89 69.2,56.35 ST2.11
P3.3
  Bottom 0.305: IC1.13 66.66,61.43 69.2,58.89 ST2.12
P3.4
  Bottom 0.305: IC1.14 66.66,63.97 69.2,61.43 ST2.13
P3.5
  Bottom 0.305: ST2.14 69.2,63.97 66.66,66.51 IC1.15
RTS-SCK
  Bottom 0.305: ST1.7 24.88,4.79 26.02,3.64 40.62,3.64 45.07,8.09 SCH1.1B 51.42,13.17 R12.1 R13.2
RXD
  Bottom 0.305: IC5.14 13.32,31.58 15.22,29.68 20.3,29.68 22.21,27.77 22.21,19.52 23.48,18.25 31.73,18.25 33.64,16.34 33.64,14.44 32.37,13.17 27.93,13.17 26.27,11.52 ST1.2
TXD-MOSI
  Bottom 0.305: 23.48,13.17 15.86,13.17 14.59,14.44 14.59,28.41 12.05,30.95 12.05,35.39 12.68,36.03 15.22,36.03 15.86,35.39 IC5.13 15.86,31.58 16.62,30.82 22.34,30.82 26.02,27.14 IC5.8 | R18.2 24.75,15.71 23.48,14.44 23.48,13.17 | 23.48,13.17 ST1.3
VCC  (via drill 0.8 pad 1.42)
  Top 0.305: v57.77,33.49 v57.77,25.87 | v41.26,96.99 v41.26,84.29 | v36.18,37.3 v36.18,30.95
  Bottom 0.305: IC6.12 43.8,26.5 43.16,27.14 38.72,27.14 | 73.65,66.51 73.65,55.97 72.76,55.08 72.76,51.78 72.25,51.27 ST2.9 | IC4.12 IC4.13 IC4.14
  Bottom 0.406: 61.58,94.45 61.58,88.73 62.85,87.47 80.63,87.47 81.9,86.19 81.9,72.86 | 81.9,72.86 83.17,71.59 R15.2 83.17,63.97 | 81.9,72.86 R9.2 | 1,48.73 ST4.31 ST4.32 IC2.20 15.86,48.73 17.77,46.82 17.77,37.94 | J2.1 75.55,71.59 C6.2 73.65,66.51 ST2.15 | 83.17,63.97 76.82,63.97 75.55,65.24 | 17.77,37.94 9.51,37.94 8.24,36.66 8.24,34.12 | 17.77,37.94 20.05,37.94 20.94,38.82 28.31,38.82 29.83,37.3 v36.18,37.3 | J1.2 90.79,65.24 89.52,63.97 83.17,63.97
  Bottom 0.61: 31.1,28.41 31.1,29.68 32.37,30.95 C3.2 | v57.77,25.87 59.04,24.6 65.39,24.6 66.66,23.33 D11.K 72.38,22.06 76.19,18.25 76.19,15.08 78.09,13.17 R17.2 ST3.2 | v57.77,33.49 55.86,33.49 53.32,30.95 IC1.40 v36.18,30.95 36.18,28.41 37.45,28.41 | C9.N 8.24,13.81 6.97,12.54 4.43,12.54 3.16,13.81 TP3.1 1,30.57 1,48.73 | IC6.14 38.72,27.14 37.45,28.41 | 13.32,90.64 2.91,90.64 1,88.73 | 75.55,65.24 C6.2 | 37.45,28.41 D12.K 31.1,28.41 | C4.2 13.32,44.92 12.05,46.19 IC2.20 | 31.1,28.41 R18.1
  Bottom 0.813: IC7.1 61.58,94.45 56.5,94.45 53.96,96.99 v41.26,96.99 14.59,96.99 13.32,95.72 C5.2 13.32,90.64 C2.P | 8.24,34.12 IC5.16 | 39.99,80.48 IC3.28 | 1,48.73 1,88.73
  Bottom 1.016: 39.99,80.48 38.72,81.75 IC4.14 v41.26,84.29

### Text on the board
Bottom: AT89S8252-Exp.-Board | JR/IEAP, Uni-Kiel
tPlace: B | A | P1.7 | P1.6 | P1.5 | P1.4 | P1.3 | P1.2 | P1.1 | P1.0 | S | P
tValues: Power | 8 x 1,5k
